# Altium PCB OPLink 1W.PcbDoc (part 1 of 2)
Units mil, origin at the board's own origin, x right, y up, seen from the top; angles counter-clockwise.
Board outline 1023.62 x 1417.32 mil, 4 copper layers (Top Layer, PWR Layer, GND Layer, Bottom Layer), stack 89.2 mil thick; 64 components, 74 nets, 299 pads, 144 vias.
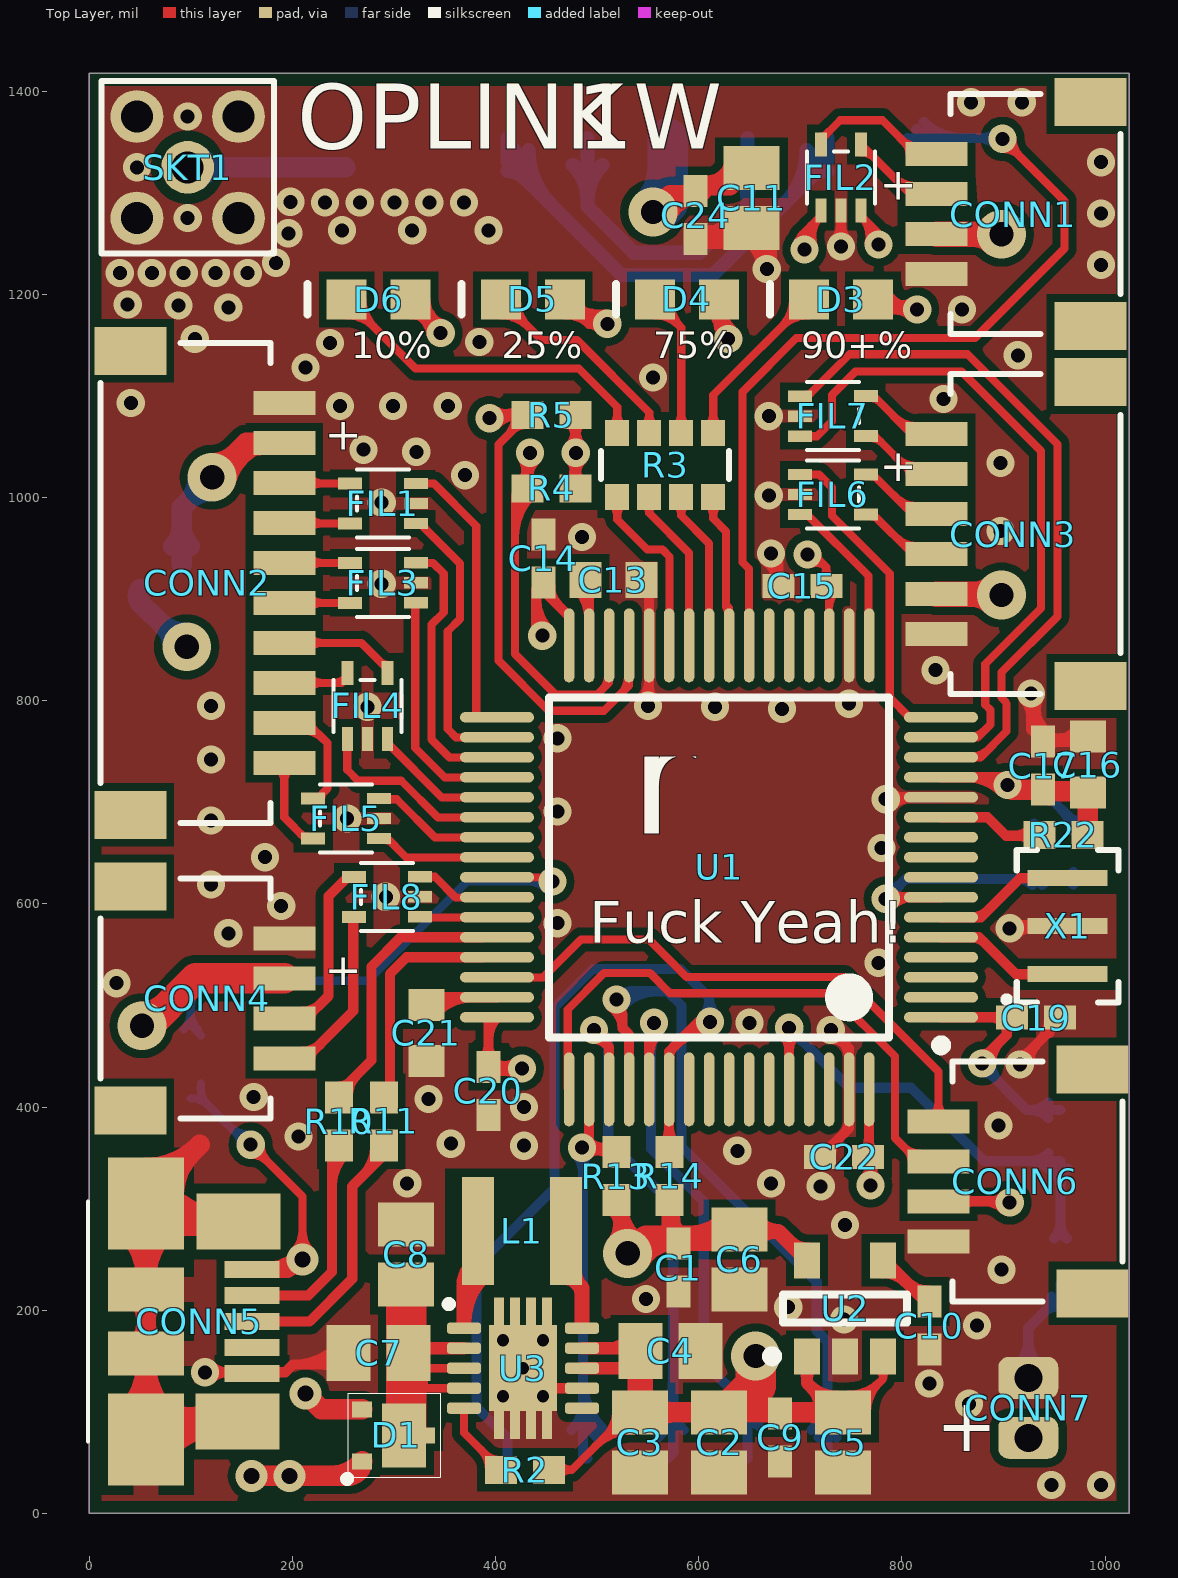
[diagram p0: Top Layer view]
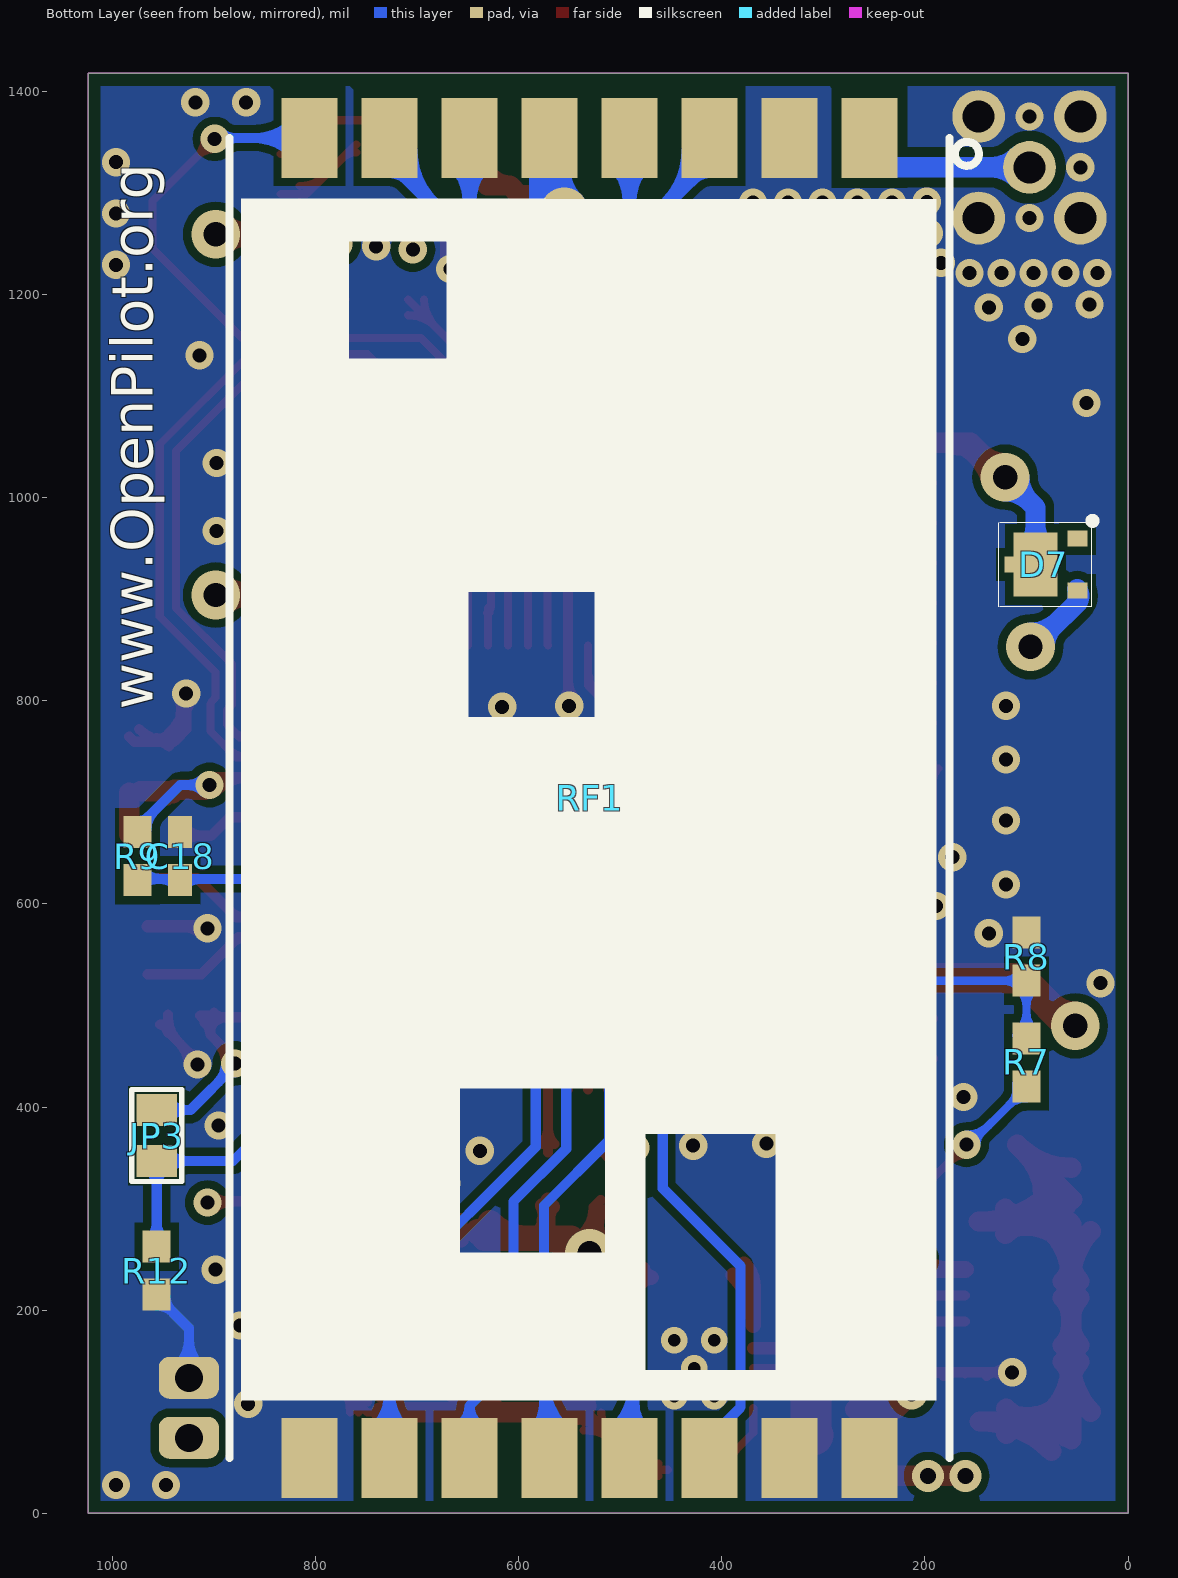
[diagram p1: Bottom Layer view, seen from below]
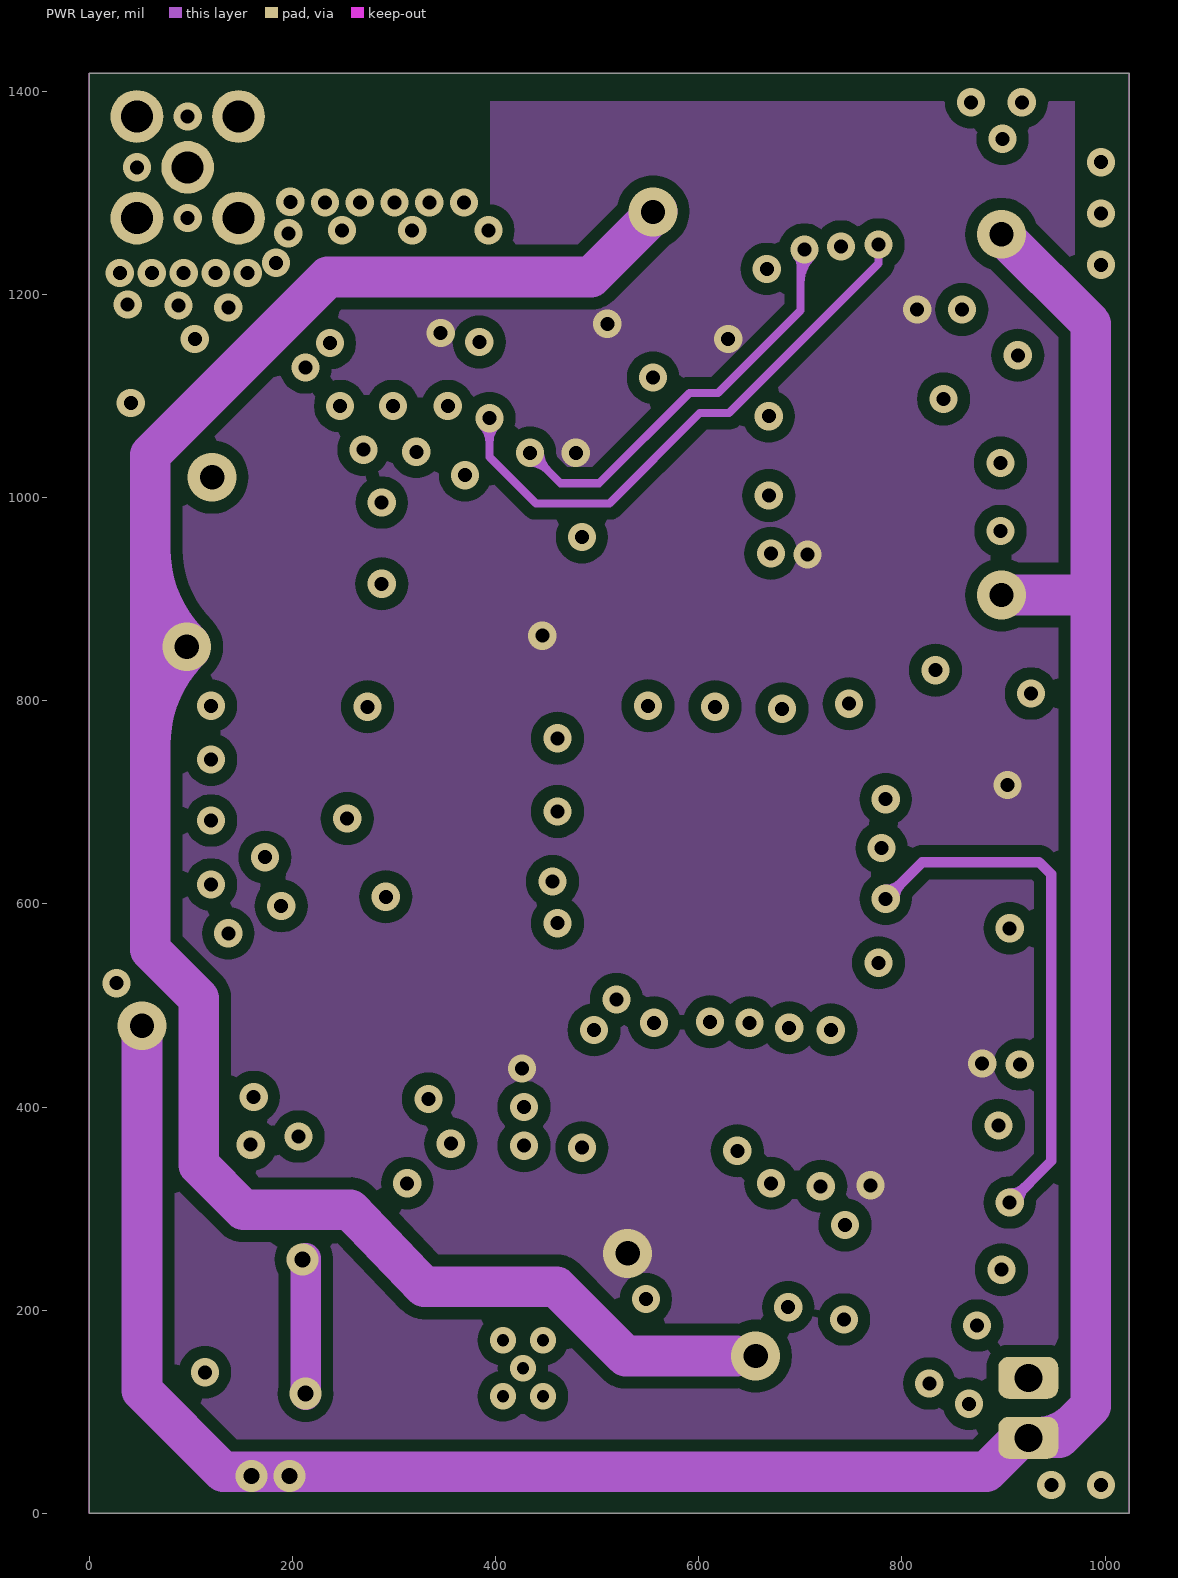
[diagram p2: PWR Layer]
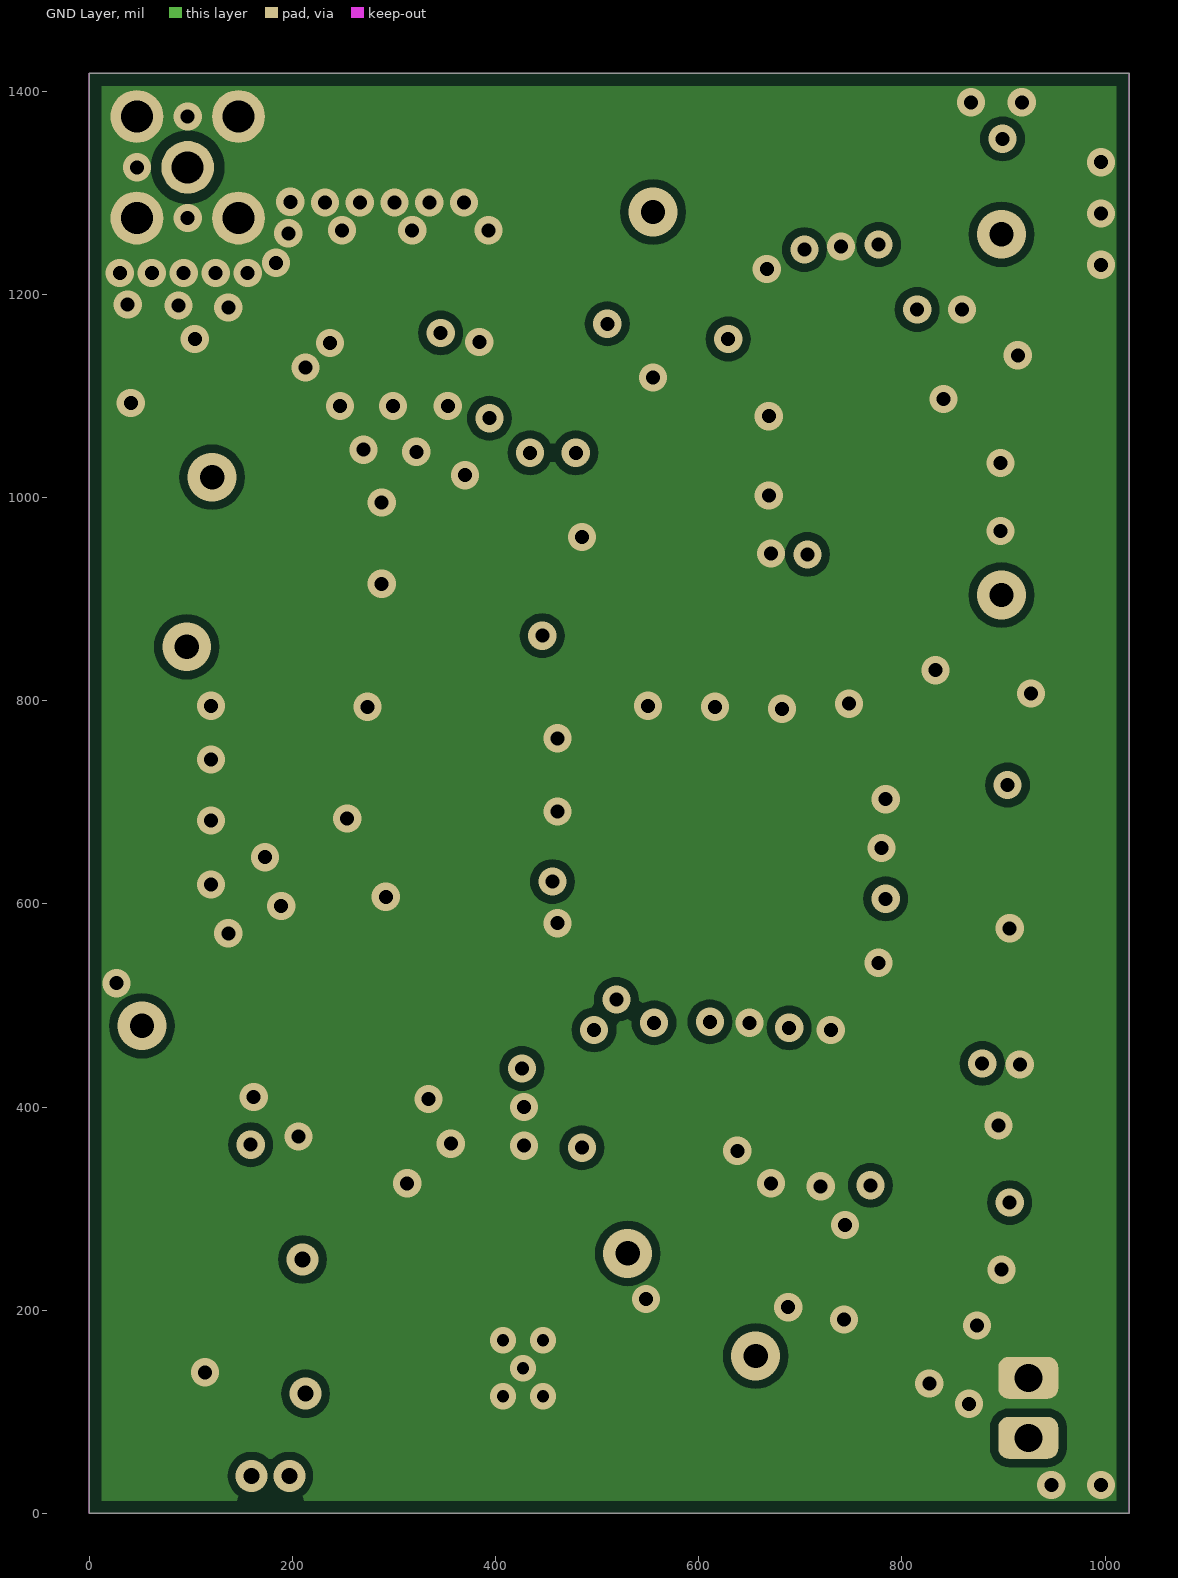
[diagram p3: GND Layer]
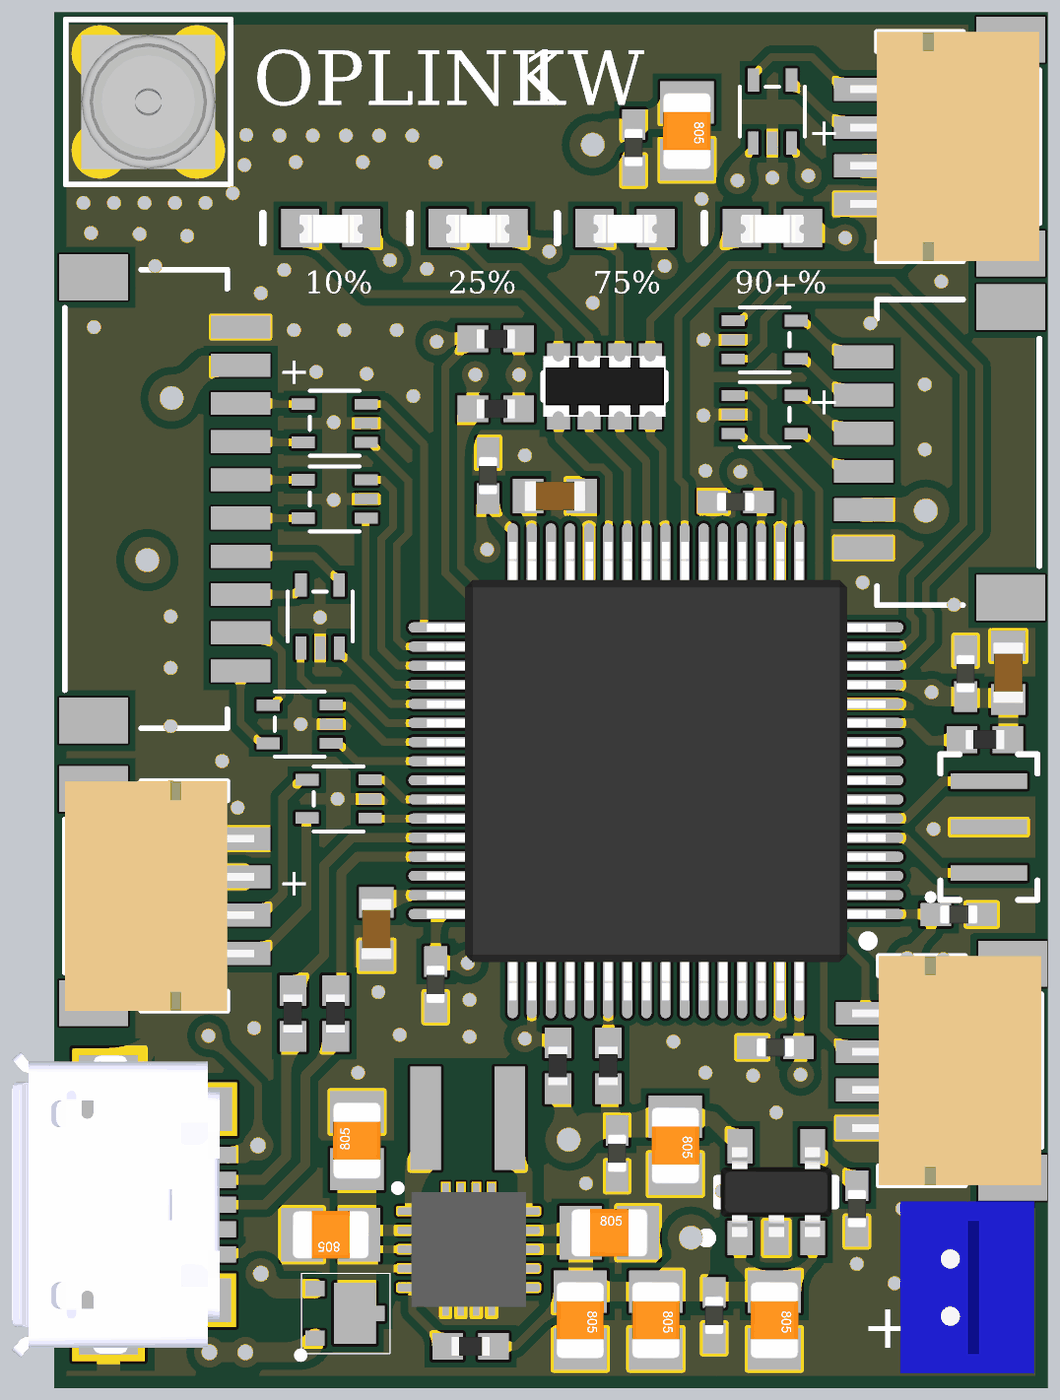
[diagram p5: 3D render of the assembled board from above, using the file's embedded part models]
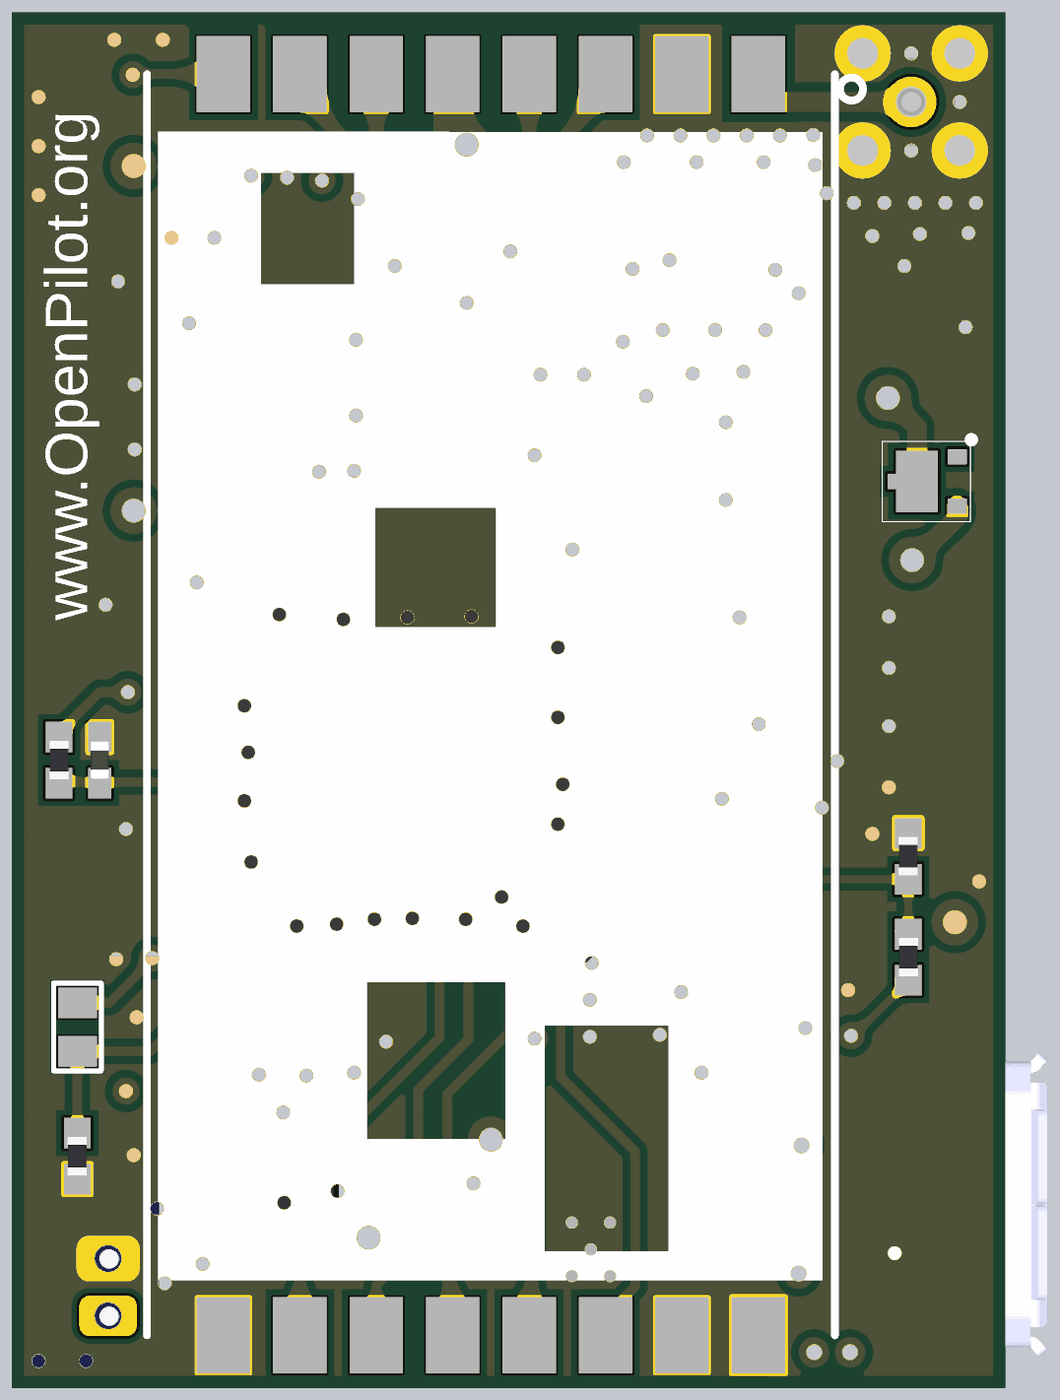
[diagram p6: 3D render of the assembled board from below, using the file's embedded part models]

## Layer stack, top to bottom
Top Layer: signal copper 1.4
Dielectric: core 58.4, FR-4, Dk 4.8
PWR Layer: signal copper 1.4
Dielectric: prepreg 12.6, FR-4, Dk 4.8
GND Layer: signal copper 1.4
Dielectric: core 12.6, FR-4, Dk 4.8
Bottom Layer: signal copper 1.4

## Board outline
0,0 1023.62,0 1023.62,1417.32 0,1417.32

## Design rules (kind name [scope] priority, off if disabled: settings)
AcuteAngle [All] p1: minimum=6.00000000000000E+0001 checktracksonly=FALSE
Clearance CPWG [InNet('ANT') vs InPolygon] p1: gap=10
Clearance Clearance_outline_power [OnLayer('PWR Layer') vs OnLayer('Keep-Out Layer')] p2: gap=15
Clearance Clearance_outline [All vs OnLayer('Keep-Out Layer')] p3: gap=12
Clearance "PWR Layer clearance" [All vs (OnLayer('PWR Layer'))] p4: gap=12
Clearance "Small Parts Clearance Poly" [(HasFootprint('SON-10') OR HasFootprint('TC164')) vs InPolygon] p5: gap=8
Clearance "Small Parts Clearance" [(HasFootprint('SON-10') OR HasFootprint('TC164'))] p6: gap=5
Clearance [All] p7: gap=8
ComponentClearance ComponentClearance_servo_headers [InComponent('JP1') or InComponent('JP2') or InComponent('JP3') or InComponent('JP4') or InComponent('JP5') or InComponent('JP6')] p1: gap=5 collisioncheckmode=3 verticalgap=10 showdistances=FALSE
ComponentClearance [All] p2: gap=10 collisioncheckmode=3 verticalgap=10 showdistances=FALSE
DiffPairsRouting [All] p1: maxlimit=20 minlimit=6 mostfreqgap=10 midlayer1_mingap=10 midlayer1_maxgap=10 midlayer2_mingap=10 midlayer2_maxgap=10 maxuncoupledlength=500
HoleSize [All] p1: absolutevalues=TRUE maxlimit=1000 minlimit=12 maxpercent=80.000 minpercent=20.000
MinimumSolderMaskSliver MinimumSolderMaskSliver_FIL1-3 [InComponent('FIL1') or InComponent('FIL2') or InComponent('FIL3')] p1: minsoldermaskwidth=1
MinimumSolderMaskSliver [All] p2: minsoldermaskwidth=3
PlaneClearance [All] p1: clearance=15
PlaneConnect [All] p1: planeconnectstyle=Direct reliefexpansion=20 reliefentries=4 reliefconductorwidth=10 reliefairgap=10
PolygonConnect PolygonConnect_usb [InComponent('CONN5')] p1: connectstyle=Relief reliefconductorwidth=24 reliefentries=4 polygonreliefangle="90 Angle" airgapwidth=10
PolygonConnect [All] p2: connectstyle=Direct reliefconductorwidth=12 reliefentries=4 polygonreliefangle="90 Angle" airgapwidth=10
RoutingVias [All] p1: holewidth=12 width=28 viastyle="Through Hole" minholewidth=12 minwidth=28 maxholewidth=28 maxwidth=50
SilkToSilkClearance SilkToSilkClearance_text [IsText] p1: silktosilkclearance=0
SilkToSilkClearance [All] p2: silktosilkclearance=4
SilkscreenOverComponentPads [All] p1: minsilkscreentomaskgap=2
SolderMaskExpansion [All] p1: expansion=3
Width [All] p1: maxlimit=400 minlimit=8 preferedwidth=10
20 further rules are at their usual default settings.

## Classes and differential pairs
differential pair USB_R: +USB_R_P -USB_R_N

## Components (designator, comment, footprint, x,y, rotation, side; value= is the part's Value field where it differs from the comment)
C1 "10n" CAP402N 580,242 r270 top
C2 "Cap805" CAP805L 620,70 r270 top
C3 "Cap805" CAP805L 542,70 r270 top
C4 "Cap805" CAP805L 572,160 r0 top
C5 "Cap805" CAP805L 742,70 r270 top
C6 "Cap805" CAP805L 640,250 r270 top
C7 "Cap805" CAP805L 285,158 r180 top
C8 "Cap805" CAP805L 312,255 r90 top
C9 "10n" CAP402N 680,75 r270 top
C10 "10n" CAP402N 827,185 r270 top
C11 "Cap805" CAP805L 652,1295 r270 top
C13 "Cap603" CAP603L 516,919 r180 top
C14 "Cap402" CAP402N 447,940 r90 top
C15 "Cap402" CAP402N 702,913 r0 top
C16 "Cap603" CAP603L 983,737 r270 top
C17 "10n" CAP402N 939,736 r90 top
C18 "Cap402" CAP402N 933,647 r270 bottom
C19 "Cap402" CAP402N 932,488 r180 top
C20 "Cap402" CAP402N 393,416 r270 top
C21 "Cap603" CAP603L 332,473 r90 top
C22 "Cap402" CAP402N 743,351 r180 top
C24 "Cap402" CAP402N 597,1278 r90 top
CONN1 "Flexi Port" "JST SH 4 Pin Side Entry" 1015,1279 r90 top
CONN2 "Flexi-IO" "JST SH 10 PIN SIDE ENTRY" 11,916 r270 top
CONN3 "UART 2 / 4 x ADC" "JST SH 6 Pin Side Entry" 1015,964 r90 top
CONN4 "Main USART" "JST SH 4 Pin Side Entry" 11,507 r270 top
CONN5 "Micro USB B" Micro_USB 56,189 r270 top
CONN6 "SWD" "JST SH 4 Pin Side Entry" 1017,327 r90 top
CONN7 "Power" "JST ZH 2 PIN TOP ENTRY" 1011,104 r90 top
D1 "PMEG2020CPA,115" 3-HUSON 310,77 r90 top
D3 "Green" LED603N 740,1195 r0 top
D4 "Yellow" LED603N 588.33,1195 r0 top
D5 "Orange" LED603N 436.67,1195 r0 top
D6 "Red" LED603N 285,1195 r0 top
D7 "PMEG2020CPA,115" 3-HUSON 91,934 r270 bottom
FIL1 "IP4256CZ5-W,115" SOT-665 289,994 r180 top
FIL2 "IP4256CZ5-W,115" SOT-665 740,1315 r90 top
FIL3 "IP4256CZ5-W,115" SOT-665 289,916 r180 top
FIL4 "IP4256CZ5-W,115" SOT-665 274,795 r90 top
FIL5 "IP4256CZ5-W,115" SOT-665 253,684 r180 top
FIL6 "IP4256CZ5-W,115" SOT-665 732,1003 r0 top
FIL7 "IP4256CZ5-W,115" SOT-665 732,1080 r0 top
FIL8 "IP4256CZ5-W,115" SOT-665 293,607 r180 top
JP3 "SBL" "TOUCH JMP 2PAD" 956,372 r0 bottom
L1 "1.5µH" IND-ASPI-3012S 426,278 r0 top
R2 "Res402" RES402N 429,43 r180 top
R3 "Res Array 330R 1206" TC164 567,1032 r0 top
R4 "Res402" RES402N 455,1009 r0 top
R5 "Res402" RES402N 455,1081 r0 top
R7 "Res402" RES402N 100,444 r90 bottom
R8 "Res402" RES402N 100,548 r270 bottom
R9 "Res402" RES402N 975,647 r90 bottom
R10 "Res402" RES402N 246,386 r270 top
R11 "Res402" RES402N 290,386 r270 top
R12 "Res402" RES402N 956,239 r270 bottom
R13 "Res402" RES402N 519,332 r270 top
R14 "Res402" RES402N 571,332 r270 top
R22 "Res402" RES402N 959,668 r180 top
RF1 "RFM23BP-S2" RFM23BP-S2 530,704 r270 bottom
SKT1 "MMCX Thru hole" MMCX_SOCKET 97,1325 r0 top
U1 "STM32F405RGT6" "STM32 64 Lead" 620,636 r180 top
U2 "LP2992-3.3" SOT23-5L 744,202 r90 top
U3 "TPS63061" SON-10 427,143 r270 top
X1 "8Mhz Ceralock" "CERALOCK 8Mhz" 963,578 r90 top

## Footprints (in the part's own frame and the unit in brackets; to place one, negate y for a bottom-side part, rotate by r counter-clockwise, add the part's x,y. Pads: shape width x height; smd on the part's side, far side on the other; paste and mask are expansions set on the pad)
3-HUSON [mm] "NXP Diode - PMEG2020CPA,115"
  rect 0.4x0.5 smd: 1(-0.65,1.05) 2(0.65,1.05)
  rect 1.6x1.1 smd: 3(0,0)
  rect 0.4x0.25 smd: 3(0,-0.65)
  silkscreen extent -1.14,-0.91 1.05,1.47, body extent -1.04,-0.91 1.04,1.4, height 0.58
CAP402N [mm] "Chip Capacitor, Body 1.0x0.5mm, IPC Medium Density"
  rect 0.8x0.6 smd: 1(-0.6,0) 2(0.6,0)
  body extent -0.5,-0.25 0.5,0.25, height 0.6
CAP603L [mm] "Chip Capacitor, Body 1.6x0.8mm, IPC High Density"
  rect 0.8x0.9 smd: 1(-0.7,0) 2(0.7,0)
  body extent -0.8,-0.4 0.8,0.4, height 0.77
CAP805L [mm] "Chip Capacitor, Body 2.0x1.3mm, IPC High Density"
  rect 1.1x1.4 smd: 1(-0.75,0) 2(0.75,0)
  body extent -1,-0.62 1,0.63, height 0.78
"CERALOCK 8Mhz" [mm] "Digikey 490-1195-1-ND"
  rect 0.4x2 smd: 1(-1.2,0) 2(1.2,0) 3(0,0)
  silkscreen extent -1.91,-1.27 1.91,1.58, body extent -1.78,-1.14 1.78,1.14, height 0.5
IND-ASPI-3012S [mm] "Inductor, Power Body 3.0x3.0x1.2mm DK: ASPI-3012S-1R5N-TCT-ND"
  rect 0.8x2.7 smd: 1(-1.1,0) 2(1.1,0)
  body extent -1.5,-1.65 1.5,1.65, height 1.4
"JST SH 4 Pin Side Entry" [mm] "SM04B-SRSS-TB"
  rect 1.2x1.8 smd paste+0 mask+0.051: 0(-2.8,0.75) 0(2.8,0.75)
  rect 0.6x1.55 smd paste+0 mask+0.051: 1(-1.5,4.6) 2(-0.5,4.6) 3(0.5,4.6) 4(1.5,4.6)
  silkscreen extent -3,0 3,4.25, body extent -3,0 3,4.95, height 2.92
"JST SH 6 Pin Side Entry" [mm] "SM06B-SRSS-TB"
  rect 1.2x1.8 smd paste+0 mask+0.051: 0(-3.8,0.75) 0(3.8,0.75)
  rect 0.6x1.55 smd paste+0 mask+0.051: 1(-2.5,4.6) 2(-1.5,4.6) 3(-0.5,4.6) 4(0.5,4.6) 5(1.5,4.6) 6(2.5,4.6)
  silkscreen extent -4,0 4,4.25, body extent -4,0 4,4.3, height 2.9
"JST SH 10 PIN SIDE ENTRY" [mm] "SM10B-SRSS-TB"
  rect 1.2x1.8 smd paste+0 mask+0.051: 0(-5.8,0.75) 0(5.8,0.75)
  rect 0.6x1.55 smd paste+0 mask+0.051: 1(-4.5,4.6) 2(-3.5,4.6) 3(-2.5,4.6) 4(-1.5,4.6) 5(-0.5,4.6) 6(0.5,4.6) 7(1.5,4.6) 8(2.5,4.6) 9(3.5,4.6) 10(4.5,4.6)
  silkscreen extent -6,0 6,4.25, body extent -6,0 6,4.25, height 2.9
"JST ZH 2 PIN TOP ENTRY" [mm] "B2B-ZR(LF)(SN) 455-1657-ND"
  rrect50% 1.05x1.5 hole 0.7 paste+0 mask+0.076: 1(-0.75,2.2) 2(0.75,2.2)
  body extent -2.26,0.03 2.24,3.53, height 4.5
LED603N [mm] "Chip LED, Body 1.6x0.8mm, IPC Medium Density"
  rect 1x1 smd: 1(-0.8,0) 2(0.8,0)
  silkscreen extent -1.78,-0.38 -1.78,0.38, body extent -0.82,-0.38 0.82,0.34, height 0.68
Micro_USB [mm] "Digikey WM17141CT-ND"
  rect 2.3x1.9 smd paste-0.178: 0(-2.946,0) 0(2.946,0)
  rect 1.4x2.1 smd paste-0.127: 0(-2.5,2.311) 0(2.5,2.286)
  rect 1.1x1.9 smd paste-0.254: 0(-0.8,0) 0(0.8,0)
  rect 0.425x1.38 smd mask+0.064: 1(-1.3,2.65) 2(-0.65,2.65) 3(0,2.65) 4(0.65,2.65) 5(1.3,2.65)
  silkscreen extent -3,-1.45 3,-1.45, body extent -3.99,-2.53 3.99,2.9, height 2.69
MMCX_SOCKET [mil] "Digikey ARF1729-ND and 07248"
  round 52 hole 31.5: 1(0,0) 2(-50,-50) 2(-50,50) 2(50,-50) 2(50,50)
  silkscreen extent -85,-85 85,85, body extent -69,-69 69,69, height 177
RES402N [mm] "Chip Resistor, Body 1.1x0.5mm, IPC Medium Density"
  rect 0.8x0.7 smd: 1(-0.6,0) 2(0.6,0)
  body extent -0.5,-0.25 0.5,0.25, height 0.27
RFM23BP-S2 [mm] "RFM23BP-S2"
  rect 2x1.4 smd mask+0.051: 1(-16.5,7) 2(-16.5,5) 3(-16.5,3) 4(-16.5,1) 5(-16.5,-1) 6(-16.5,-3) 7(-16.5,-5) 8(-16.5,-7) 9(16.5,-7) 10(16.5,-5) 11(16.5,-3) 12(16.5,-1) 13(16.5,1) 14(16.5,3) 15(16.5,5)
  rect 2x1.4 smd: 16(16.5,7)
  silkscreen extent -16.5,-9 16.5,9.73, body extent -16.5,-9 16.5,9, height 1.9
SON-10 [mm] "SON, 10-Leads, Body 3x3 mm, Pitch 0.5mm, IPC High Density"
  rect 0.7x0.25 smd paste-0.04 mask+0.051: 0(-1.422,0.6) 0(-1.422,-0.2) 0(-1.422,0.2) 0(-1.422,-0.6) 0(1.422,0.6) 0(1.422,-0.2) 0(1.422,0.2) 0(1.422,-0.6)
  rect 2.15x1.7 smd paste-0.076 mask+0.051: 0(0,0)
  rrect50% 0.28x0.85 smd paste-0.04 mask+0.064: 1(-1,-1.475) 2(-0.5,-1.475) 3(0,-1.475) 4(0.5,-1.475) 5(1,-1.475) 9(-0.5,1.475) 10(-1,1.475)
  rrect50% 0.28x0.85 smd paste-0.04 mask+0.07: 6(1,1.475) 7(0.5,1.475) 8(0,1.475)
  silkscreen extent -1.65,-1.91 -1.55,-1.8, body extent -1.5,-1.5 1.5,1.5, height 0.75
SOT23-5L [mm] "SOT23, 5-Leads, Body 2.9x1.6mm, Pitch 0.95mm, Lead Span 2.8mm, IPC High Density"
  rect 0.9x0.65 smd mask+0.076: 1(-1.2,0.95) 2(-1.2,0) 3(-1.2,-0.95) 4(1.2,-0.95) 5(1.2,0.95)
  silkscreen extent -1.32,-1.55 0.35,1.95, body extent -1.17,-1.46 1.17,1.46, height 0.97
SOT-665 [mm] "NXP SOT665"
  rect 0.6x0.28 smd mask+0.076: 1(-0.825,0.5) 2(-0.825,0) 3(-0.825,-0.5)
  rect 0.6x0.3 smd mask+0.076: 4(0.825,-0.5) 5(0.825,0.5)
  silkscreen extent -0.65,-0.85 0.65,0.85, body extent -0.65,-0.85 0.65,0.85, height 0.6
"STM32 64 Lead" [mm] "Thin QFP, 64-Leads, Body 10x10mm, Pitch 0.5mm, IPC Medium Density"
  oval 1.85x0.265 smd mask+0.076: 1(-5.55,3.75) 2(-5.55,3.25) 3(-5.55,2.75) 4(-5.55,2.25) 5(-5.55,1.75) 6(-5.55,1.25) 7(-5.55,0.75) 8(-5.55,0.25) 9(-5.55,-0.25) 10(-5.55,-0.75) 11(-5.55,-1.25) 12(-5.55,-1.75) 13(-5.55,-2.25) 14(-5.55,-2.75) 15(-5.55,-3.25) 16(-5.55,-3.75) 33(5.55,-3.75) 34(5.55,-3.25) 35(5.55,-2.75) 36(5.55,-2.25) 37(5.55,-1.75) 38(5.55,-1.25) 39(5.55,-0.75) 40(5.55,-0.25) 41(5.55,0.25) 42(5.55,0.75) 43(5.55,1.25) 44(5.55,1.75) 45(5.55,2.25) 46(5.55,2.75) 47(5.55,3.25) 48(5.55,3.75)
  oval 0.265x1.85 smd mask+0.076: 17(-3.75,-5.55) 18(-3.25,-5.55) 19(-2.75,-5.55) 20(-2.25,-5.55) 21(-1.75,-5.55) 22(-1.25,-5.55) 23(-0.75,-5.55) 24(-0.25,-5.55) 25(0.25,-5.55) 26(0.75,-5.55) 27(1.25,-5.55) 28(1.75,-5.55) 29(2.25,-5.55) 30(2.75,-5.55) 31(3.25,-5.55) 32(3.75,-5.55) 49(3.75,5.55) 50(3.25,5.55) 51(2.75,5.55) 52(2.25,5.55) 53(1.75,5.55) 54(1.25,5.55) 55(0.75,5.55) 56(0.25,5.55) 57(-0.25,5.55) 58(-0.75,5.55) 59(-1.25,5.55) 60(-1.75,5.55) 61(-2.25,5.55) 62(-2.75,5.55) 63(-3.25,5.55) 64(-3.75,5.55)
  silkscreen extent -5.68,-4.25 4.25,4.57, body extent -6.01,-5.99 5.99,6.01, height 1.7
TC164 [mm] "4-Resistor Array"
  rect 0.6x0.65 smd mask+0.064: 1(-1.2,-0.8) 2(-0.4,-0.8) 3(0.4,-0.8) 4(1.2,-0.8) 5(1.2,0.8) 6(0.4,0.8) 7(-0.4,0.8) 8(-1.2,0.8)
  silkscreen extent -1.6,-0.35 1.6,0.35, body extent -1.6,-0.8 1.6,0.8, height 0.55
"TOUCH JMP 2PAD" [mil] "Touch Jumper 2 Pad"
  rect 40x31.5 smd mask+2: 1(0,25) 2(0,-25)
  silkscreen extent -25,-45 25,45

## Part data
C1 C9 C10 C17: library part Cap402, "Capacitor SMD"
C2 C3 C4 C5 C6 C7 C8 C11 C13 C14 C15 C16 C18 C19 C20 C21 C22 C24: "Capacitor SMD"
CONN1 CONN4 CONN6: library part "JST-SH 4-pin Side Entry Socket", "JST-SH 4-pin Side Entry Socket"
CONN2: library part "JST-SH 10-pin Side Entry Socket", "JST-SH 10-pin Side Entry Socket"
CONN3: library part "JST-SH 6-pin Side Entry Socket", "JST-SH 6-pin Side Entry Socket"
CONN5: library part "USB Micro B SMT", "USB Micro B SMT Socket"
CONN7: library part "JST ZH 2-pin Top Entry Socket", "JST ZH 1.5mm 2-pin TopEntry Socket"
D1 D7: "Dual Diode Command Cathode 2A"
D3: library part "LED 603 Gr", "Green 603 LED"
D4: library part "LED 603 Yellow", "Yellow 603 LED"
D5: library part "LED 603 Or", "Orange 603 LED"
D6: library part "LED 603 Red", "Red 603 LED"
FIL1 FIL2 FIL3 FIL4 FIL5 FIL6 FIL7 FIL8: library part "RF Filter 100R 30pF", "IP4256CZ5-W,115 2 channel, 100R, 30pF, RF ESD Filter"
JP3: library part "2 PAD Touch JMP", "2 Pad Touch Jumper"
L1: library part "Pwr Inductor 1.5µH", "Power Inductor 1.5µH"
R2 R4 R5 R7 R8 R9 R10 R11 R12 R13 R14 R22: "Resistor SMD"
R3: library part "Res Array 330R", "4 Resistor Array"
RF1: "UHF 1W Transceiver"
SKT1: "MMCX Socket"
U1: library part STM32F103RET6, "STM32 ARM-based 32-bit MCU with 1MB Flash, 64-pin LQFP, Industrial Temperature"
U2: "3.3V 250mA LDO Regulator"
X1: library part CERALOCK8, "Ceralock 8Mhz with caps"

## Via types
v1: diameter 27.8, hole 13.78, Top Layer to Bottom Layer, tented both sides, 127 vias
v2: diameter 48, hole 24, Top Layer to Bottom Layer, tented both sides, 8 vias
v3: diameter 31.5, hole 15.75, Top Layer to Bottom Layer, tented both sides, 4 vias
v4: diameter 25.98, hole 12, Top Layer to Bottom Layer, tented bottom, 4 vias
v5: diameter 26, hole 12, Top Layer to Bottom Layer, tented bottom, 1 vias

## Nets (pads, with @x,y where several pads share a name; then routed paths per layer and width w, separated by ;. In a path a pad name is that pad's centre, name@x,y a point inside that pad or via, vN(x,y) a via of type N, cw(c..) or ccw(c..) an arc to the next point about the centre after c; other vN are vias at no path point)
ANT: RF1.1 SKT1.1 | length 215.7
  Bottom Layer w20: SKT1.1@97,1325 RF1.1@252,1325 ; SKT1.1@108.31,1313.69 cw(c135.63,1286.37) 135.63,1325 cw(c135.63,1363.63) SKT1.1@108.31,1336.31
GND: C1.2 C2.2 C3.2 C4.2 C5.2 C6.2 C7.2 C8.2 C9.2 C10.2 C11.2 C13.1 C14.2 C15.1 C16.1 C17.2 C18.1 C19.1 C20.2 C21.1 C22.2 C24.1 CONN1.1 CONN2.1 CONN3.1 CONN4.1 CONN5.0 CONN5.5 CONN6.1 CONN7.2 FIL1.2 FIL2.2 FIL3.2 FIL4.2 FIL5.2 FIL6.2 FIL7.2 FIL8.2 R8.1 R12.2 RF1.2 RF1.9 RF1.15 RF1.16 SKT1.2 U1.12 U1.18 U1.28 U1.63 U2.2 U3.0 U3.7 X1.3 | length 3538
  Top Layer w10: v1(114,139) 159.15,139 CONN5.5@160.33,137.82 161.51,139 193,139 200.75,146.75 244.22,146.75 C7.2@255.47,158 ; v1@120.29,132.71 cw(c135.48,117.52) 135.48,139 cw(c135.48,160.48) v1@120.29,145.29 ; 130.55,139 cw(c130.55,126.84) CONN5.5@139.15,135.44 ; CONN5.5@181.51,135.44 cw(c190.11,126.84) 190.11,139 ; 202.36,146.75 ccw(c202.36,205.21) C7.2@243.7,163.87 ; 226.5,146.75 ccw(c226.5,181.06) C7.2@250.77,156.8 ; 228.17,146.75 cw(c228.17,124.8) C7.2@243.7,140.32 ; v5(427,143) 446.68,123.32 U3.7@485.07,123.32 ; C13.1@543.56,919 551.1,911.46 U1.28@551.1,854.5 551.1,796.1 v1(550,795) ; v1@543.71,801.29 ccw(c525.86,819.14) U1.28@551.1,819.14 ; 551.1,813.82 ccw(c568.82,813.82) v1@556.29,801.29 ; v1@665.61,937.92 cw(c646.01,912.16) C15.1@678.38,912.16 ; v1(671,945) 678.38,937.62 C15.1@678.38,913 ; v1@671.67,945.88 cw(c661.36,932.34) 678.38,932.34 ; C15.1@673.56,917.82 ccw(c661.93,929.44) 678.38,929.44 ccw(c694.82,929.44) C15.1@683.19,917.82 ; C22.2@722.38,355 724,355 747.95,378.95 U1.63@747.95,417.5 747.95,458.05 v1(730,476) ; v1@730,467.1 cw(c730,445.62) 745.19,460.81 cw(c760.38,476) v1@738.9,476 ; C22.2@730.13,351 cw(c754.57,351) 737.29,368.29 ; v1@732.07,467.35 cw(c734.2,458.44) 742.13,463.02 ; v1@733.71,1253.29 ccw(c718.52,1268.48) 740,1268.48 ccw(c761.48,1268.48) v1@746.29,1253.29 ; v1(740,1247) FIL2.2@740,1282.52 ; 740.97,465.03 cw(c724.64,448.7) U1.63@747.74,448.7 ; 742.39,373.39 ccw(c729.49,386.3) U1.63@747.74,386.3 ; v1(784,703) 785.9,704.9 U1.12@838.5,704.9 ; v1@790.29,696.71 cw(c810.06,676.94) U1.12@810.06,704.9 ; v1@790.29,709.29 ccw(c800.9,719.9) 800.9,704.9 ; v1(906,576) v1@908,578 ; v1@916,450.9 ccw(c916,464.22) 925.42,454.8 ; v1@916.31,445.69 945,474.38 ; v1@920.71,800.71 cw(c905.52,785.52) 927,785.52 cw(c948.48,785.52) v1@933.29,800.71 ; v1@922.55,799.29 cw(c911.81,780.69) 932.56,786.25 cw(c953.31,791.81) v1@934.71,802.55 ; v1@924.9,442 cw(c954.53,442) 933.58,462.96 ; 927,783.91 ccw(c958.09,783.91) C17.2@936.82,761.23 ; 935.15,464.53 ccw(c911.68,488) C19.1@944.87,488 ; C17.2@936.32,769.82 cw(c932.99,777.61) 927,771.62 ; C17.2@943.16,759.62 ccw(c943.16,802.43) C16.1@973.43,772.16 ; C17.2@943.66,768.53 cw(c979.75,807) v1(927,807) 927,771.62 ; C17.2@943.82,754.81 cw(c955.44,743.18) 955.44,759.62 cw(c955.44,776.07) C17.2@943.82,764.44 ; C17.2@944.58,767.47 ccw(c953.56,773.77) 956.4,763.17 ; 945,472.83 cw(c953.47,472.83) C19.1@952.48,481.24 ; C19.1@945,491 945,474.38 ; C19.1@946,484.25 cw(c939.45,479.93) 945,474.38 ; C16.1@983,764.56 978.06,759.62 C17.2@939,759.62 927,771.62
  Top Layer w12: v1@908,578 X1.3@965,578 ; v1@911.58,570.42 cw(c929.89,552.11) X1.3@929.89,578 ; v1@911.58,581.58 ccw(c920.24,590.24) 920.24,578
  Top Layer w20: CONN5.0@36.62,100.25 ccw(c-10.15,147.03) 56,147.03 ccw(c122.15,147.03) 75.38,100.25 ccw(c98.73,123.61) 98.73,90.57 ; CONN5.0@36.62,277.75 cw(c-10.15,230.97) 56,230.97 cw(c122.15,230.97) 75.38,277.75 cw(c98.73,254.39) 98.73,287.43 ; CONN5.0@47.76,149.26 cw(c27.87,129.37) 56,129.37 cw(c84.13,129.37) CONN5.0@64.24,149.26 ; CONN5.0@47.76,165.74 ccw(c27.87,185.64) 56,185.64 ccw(c84.13,185.64) CONN5.0@64.24,165.74 ; CONN5.0@47.76,212.26 cw(c27.87,192.36) 56,192.36 cw(c84.13,192.36) CONN5.0@64.24,212.26 ; CONN5.0@47.76,228.74 ccw(c27.87,248.63) 56,248.63 ccw(c84.13,248.63) CONN5.0@64.24,228.74 ; CONN5.0@55,309 109,363 ; CONN5.0@56,340.28 ccw(c56,413.37) 107.68,361.68 ; CONN5.0@61.23,75.64 cw(c97.29,39.59) 97.29,90.57 ; CONN5.0@61.23,302.36 ccw(c97.29,338.41) 97.29,287.43 ; CONN5.0@71.49,103.47 ccw(c99.32,144.05) 112.05,96.53 ccw(c124.23,51.09) CONN5.0@81.11,69.91 ; CONN5.0@71.51,274.53 cw(c99.72,233.44) 112.62,281.59 cw(c125.19,328.5) CONN5.0@80.96,308.44 ; CONN5.0@75.38,61.5 cw(c145.57,-8.7) CONN5.0@145.57,90.57 ; CONN5.0@75.38,316.5 ccw(c145.57,386.7) CONN5.0@145.57,287.43 ; CONN5.0@83.4,312.87 cw(c142.62,312.87) 100.74,354.75 ; CONN5.0@119.8,78.16 ccw(c89.83,48.18) 89.83,90.57 ccw(c89.83,132.97) CONN5.0@119.8,102.99 ; CONN5.0@120.8,275.01 ccw(c90.83,245.03) 90.83,287.43 ccw(c90.83,329.82) CONN5.0@120.8,299.84 ; CONN5.0@146,90.57 73.57,90.57 CONN5.0@56,73 CONN5.0@56,157.5 CONN5.0@56,220.5 56,285 58.43,287.43 CONN5.0@147,287.43 ; C24.1@597.91,1259.88 ccw(c606.58,1274.92) 611.08,1258.15 ; C11.2@637.2,1273.01 cw(c597,1307.07) C24.1@597,1254.38 640.91,1254.38 C11.2@652,1265.47 654.53,1265.47 667,1253 v1(667,1225) ; C11.2@650.92,1256.15 cw(c626.82,1223.99) v1@667,1223.99
  Bottom Layer w10: CONN7.2@913.31,144.61 ccw(c886.56,171.36) 924.39,171.36 ccw(c962.21,171.36) CONN7.2@935.47,144.61 ; CONN7.2@924.39,133.53 924.39,182.39 956,214 R12.2@956,226.38 ; C18.1@930,671.62 C18.1@930,678.96 ; 940,198 cw(c956,182.01) R12.2@956,204.63 ; 941.43,199.43 ccw(c927.45,213.41) R12.2@947.22,213.41
  other v1: 947,28 996,28 866,108 827,128 874,185 743,191 688,203 548,211 898,240 744,284 720,322 313,325 671,325 638,357 428,362 356,364 206,371 895,382 428,400 334,408 162,410 916,442 650,483 27,522 777,542 137,571 461,581 189,598 292,607 120,619 173,646 780,655 120,682 254,684 461,691 120,742 461,763 682,792 274,794 616,794 120,795 748,797 833,830 288,915 485,961 897,967 288,995 669,1002 370,1022 897,1034 322,1045 270,1047 669,1080 247,1090 299,1090 353,1090 41,1093 841,1097 555,1118 213,1128 914,1140 237,1152 384,1153 104,1156 859,1185 137,1187 88,1189 38,1190 30.2,1221 61.65,1221 93.1,1221 124.55,1221 156,1221 996,1229 184,1231 196,1260 249,1263 318,1263 393,1263 97,1275 996,1279.5 232.2,1290.36 266.4,1290.36 300.6,1290.36 334.8,1290.36 369,1290.36 198,1291 47,1325 996,1330 97,1375 868,1389 918,1389
  other v4: 407.32,115.44 446.68,115.44 407.32,170.56 446.68,170.56
GPIO_2: RF1.8 U1.23 | length 1062.5
  Top Layer w8: 643.1,1104.1 643.1,936.27 649.53,929.85 U1.23@649.53,854.5 ; 643.5,1104.5 696,1157 872,1157 960,1245 960,1292 899.5,1352.5 v1@899.5,1353.5 ; v1@899,1343.1 cw(c899,1319.21) 915.9,1336.1 cw(c932.79,1353) v1@908.9,1353
  Bottom Layer w10: RF1.8@805.59,1353.61 RF1.8@813.2,1346 ; RF1.8@811.2,1354 v1@898,1354 ; RF1.8@814.47,1344.73 cw(c836.86,1322.34) 836.86,1354 ; RF1.8@814.47,1362.49 ccw(c834.96,1382.98) 834.96,1354 ; RF1.8@821.54,1337.65 cw(c861,1298.19) 861,1354 ; RF1.8@821.54,1369.56 ccw(c859.1,1407.12) 859.1,1354 ; 875.11,1354 cw(c875.11,1329.11) v1@892.71,1346.71 ; 879.93,1354 ccw(c879.93,1372.07) v1@892.71,1359.29
  other v1: 899,1353
NetC10_1: C10.1 U2.4 | length 114.6
  Top Layer w12: U2.4@781.4,237.53 cw(c781.4,205.97) 803.71,228.29 ; U2.4@781.4,249.24 782.76,249.24 823.38,208.62 C10.1@829,208.62 ; 804.18,227.82 ccw(c827,250.65) C10.1@827,218.37
NetC13_2: C13.2 U1.31 | length 106.7
  Top Layer w10: C13.2@480.84,909.43 cw(c453.79,882.38) U1.31@492.05,882.38 ; C13.2@488.44,919 492.05,915.39 U1.31@492.05,854.5 ; 492.05,899.79 cw(c505.68,899.79) C13.2@496.04,909.43
NetC21_2: C21.2 U1.47 | length 134.6
  Top Layer w10: C21.2@332,500.56 339.49,508.05 U1.47@401.5,508.05 ; C21.2@334.5,500.03 cw(c353.85,480.68) 353.85,508.05 ; C21.2@341.57,492.96 cw(c377.99,456.53) U1.47@377.99,508.05
NetCONN1_3: CONN1.3 FIL2.4 | length 149.2
  Top Layer w8: FIL2.4@759.68,1339.67 cw(c759.68,1320.81) 773.02,1334.15 ; FIL2.4@759.68,1347.48 808.48,1298.68 CONN1.3@833.9,1298.68 ; 790.4,1316.77 ccw(c815.2,1341.57) CONN1.3@815.2,1306.5 ; CONN1.3@804.05,1303.11 ccw(c815.2,1314.25) CONN1.3@815.2,1298.5
NetCONN1_4: CONN1.4 FIL2.5 | length 181.1
  Top Layer w8: FIL2.5@719.52,1342 719.52,1351.52 739.29,1371.29 780.71,1371.29 813.94,1338.06 CONN1.4@833.9,1338.06 ; FIL2.5@720.32,1355.29 ccw(c720.32,1362.48) FIL2.5@725.4,1357.4 ; 799.73,1352.27 ccw(c815.2,1367.75) CONN1.4@815.2,1345.87 ; 802.75,1349.25 cw(c791.55,1338.06) CONN1.4@807.39,1338.06
NetCONN2_2: CONN2.2 D7.3 | length 435.4
  Top Layer w20: v2(121,1020) 154.8,1053.8 CONN2.2@192.1,1053.8 ; v2@121,1034 ccw(c121,1067.8) 144.9,1043.9 ccw(c168.8,1020) v2@135,1020 ; v2@134.52,1016.38 cw(c188.35,1001.95) 160.49,1050.21 ; v2@134.65,1023.11 cw(c149.24,1026.44) 141.76,1039.4 ; 138.55,1037.55 cw(c173.4,1002.69) CONN2.2@173.4,1051.98
  Bottom Layer w20: D7.3@82.76,952.08 ccw(c62.87,971.98) 91,971.98 ccw(c119.13,971.98) D7.3@99.24,952.08 ; D7.3@91,934 91,990 v2(121,1020) ; v2@107,1020 cw(c73.2,1020) 97.1,996.1 cw(c121,972.2) v2@121,1006
NetCONN2_3: CONN2.3 FIL1.4 | length 94.3
  Top Layer w8: CONN2.3@192.1,1014.43 192.84,1013.68 FIL1.4@256.52,1013.68 ; CONN2.3@216.33,1008.9 cw(c227.87,997.35) 227.87,1013.68 ; CONN2.3@216.33,1019.95 ccw(c231.45,1035.07) 231.45,1013.68
NetCONN2_4: CONN2.4 FIL1.5 | length 94.3
  Top Layer w8: CONN2.4@192.1,975.06 192.84,974.32 FIL1.5@256.52,974.32 ; CONN2.4@216.33,969.53 cw(c227.87,957.98) 227.87,974.31 ; CONN2.4@216.33,980.58 ccw(c231.45,995.7) 231.45,974.31
NetCONN2_5: CONN2.5 FIL3.4 | length 94
  Top Layer w8: CONN2.5@192.1,935.68 FIL3.4@256.52,935.68 ; CONN2.5@216.33,930.16 cw(c229.66,916.83) 229.66,935.68 cw(c229.66,954.54) CONN2.5@216.33,941.21
NetCONN2_6: CONN2.6 FIL3.5 | length 94
  Top Layer w8: CONN2.6@192.1,896.32 FIL3.5@256.52,896.32 ; CONN2.6@216.33,890.79 cw(c229.66,877.46) 229.66,896.31 cw(c229.66,915.17) CONN2.6@216.33,901.84
NetCONN2_7: CONN2.7 FIL4.4 | length 153.2
  Top Layer w8: CONN2.7@192.1,856.94 268.06,856.94 293.68,831.32 FIL4.4@293.68,827.48 ; CONN2.7@216.33,851.42 cw(c229.66,838.09) 229.66,856.94 cw(c229.66,875.8) CONN2.7@216.33,862.47 ; 286.9,838.1 ccw(c293.68,844.89) FIL4.4@293.68,835.29
NetCONN2_8: CONN2.8 FIL4.5 | length 112.7
  Top Layer w8: CONN2.8@192.1,817.57 248.57,817.57 254.32,823.32 FIL4.5@254.32,827.48 ; CONN2.8@216.33,812.05 cw(c229.66,798.72) 229.66,817.57 cw(c229.66,836.43) CONN2.8@216.33,823.1 ; 240.06,817.57 ccw(c240.06,835.83) FIL4.5@252.97,822.92
NetCONN2_9: CONN2.9 FIL5.4 | length 148.6
  Top Layer w8: CONN2.9@192.1,778.2 214.6,778.2 234.61,758.19 234.61,713.61 223.5,702.5 FIL5.4@222.5,702.5 ; CONN2.9@210.8,770.39 cw(c210.8,742.37) 230.62,762.19 ; CONN2.9@218.61,778.2 ccw(c228.31,778.2) CONN2.9@221.45,771.35 ; FIL5.4@228.33,703.68 cw(c237.13,703.68) 230.91,709.91
NetCONN2_10: CONN2.10 FIL5.5 | length 127.8
  Top Layer w8: CONN2.10@186.58,733.31 cw(c173.24,719.98) 192.1,719.98 cw(c210.96,719.98) CONN2.10@197.63,733.31 ; CONN2.10@192.1,738.83 192.1,684.9 212.68,664.32 FIL5.5@220.52,664.32 ; 208.07,668.93 ccw(c214.61,675.48) FIL5.5@214.61,666.22
NetCONN3_3: CONN3.3 FIL6.4 | length 115
  Top Layer w8: FIL6.4@764.48,983.32 771.68,983.32 810.68,944.32 CONN3.3@833.9,944.32 ; FIL6.4@770.39,981.41 cw(c770.39,973.67) FIL6.4@775.86,979.14 ; 794.16,960.84 ccw(c815.2,981.88) CONN3.3@815.2,952.13
NetCONN3_4: CONN3.4 FIL6.5 | length 115
  Top Layer w8: FIL6.5@764.48,1022.68 771.32,1022.68 810.32,983.68 CONN3.4@833.9,983.68 ; FIL6.5@770.39,1020.78 cw(c770.39,1013.94) FIL6.5@775.22,1018.78 ; 793.53,1000.47 ccw(c815.2,1022.14) CONN3.4@815.2,991.5
NetCONN3_5: CONN3.5 FIL7.4 | length 124.3
  Top Layer w8: FIL7.4@764.48,1060.32 773.68,1060.32 810.94,1023.06 CONN3.5@833.9,1023.06 ; FIL7.4@770.39,1058.41 cw(c770.39,1045.84) 779.27,1054.73 ; 794.6,1039.4 ccw(c815.2,1059.99) CONN3.5@815.2,1030.87 ; CONN3.5@804.87,1029.13 cw(c798.79,1023.06) CONN3.5@807.39,1023.06
NetCONN3_6: CONN3.6 FIL7.5 | length 117.6
  Top Layer w8: FIL7.5@764.48,1099.68 772.32,1099.68 809.57,1062.43 CONN3.6@833.9,1062.43 ; FIL7.5@770.39,1097.78 cw(c770.39,1088.52) 776.93,1095.07 ; 792.27,1079.73 ccw(c815.2,1102.67) CONN3.6@815.2,1070.24
NetCONN4_3: CONN4.3 FIL8.4 | length 204.1
  Top Layer w10: CONN4.3@192.1,487.32 213.44,487.32 235.71,509.58 235.71,607.71 FIL8.4@255,627 ; CONN4.3@210.8,494.13 ccw(c210.8,516.93) 226.93,500.81 ; CONN4.3@217.61,487.32 cw(c227.69,487.32) CONN4.3@220.57,494.44
NetCONN4_4: CONN4.4 FIL8.5 | length 205.5
  Top Layer w10: CONN4.4@192.1,447.94 213.44,447.94 260,494.51 FIL8.5@260,587 ; CONN4.4@210.8,454.76 ccw(c210.8,477.56) 226.93,461.44 ; CONN4.4@217.61,447.94 cw(c227.69,447.94) CONN4.4@220.57,455.07
NetD3_1: D3.1 R3.5 | length 259.6
  Top Layer w8: R3.5@608.72,1070 ccw(c595.39,1083.34) 614.24,1083.34 ccw(c633.1,1083.34) R3.5@619.77,1070 ; R3.5@614.24,1063.5 614.24,1100.74 D3.1@708.5,1195 ; D3.1@692.82,1195 cw(c654.95,1195) 681.73,1168.22 cw(c708.5,1141.45) D3.1@708.5,1179.32
NetD4_1: D4.1 R3.6 | length 237.6
  Top Layer w8: D4.1@556.84,1179.32 cw(c556.84,1145.88) 580.48,1169.52 ; D4.1@560,1190 582.75,1167.25 ; D4.1@564.51,1194.57 ccw(c583.7,1193.48) D4.1@570.11,1179.89 ; D4.1@572.5,1194.12 ccw(c607.63,1192.13) 582.75,1167.25 ; R3.6@577.22,1070 ccw(c563.89,1083.34) 582.75,1083.34 ccw(c601.61,1083.34) R3.6@588.27,1070 ; R3.6@582.75,1063.5 582.75,1167.25
NetD5_1: D5.1 R3.7 | length 301.5
  Top Layer w8: D5.1@405.17,1179.32 cw(c405.17,1141.45) 431.95,1168.22 cw(c458.72,1195) D5.1@420.86,1195 ; D5.1@405.17,1195 445.31,1154.86 480.14,1154.86 551.25,1083.75 R3.7@551.25,1063.5 ; R3.7@545.73,1070 ccw(c532.39,1083.34) 551.25,1083.34 ccw(c570.11,1083.34) R3.7@556.78,1070
NetD6_1: D6.1 R3.8 | length 424.9
  Top Layer w8: D6.1@253.5,1179.32 cw(c253.5,1141.45) 280.28,1168.22 cw(c307.06,1195) D6.1@269.19,1195 ; D6.1@253.5,1195 321.4,1127.1 481.9,1127.1 519.76,1089.24 R3.8@519.76,1063.5 ; R3.8@514.23,1070 ccw(c500.9,1083.34) 519.76,1083.34 ccw(c538.61,1083.34) R3.8@525.28,1070
NetFIL1_1: FIL1.1 U1.34 | length 286.4
  Top Layer w8: FIL1.1@321.48,974.32 325.68,974.32 365,935 365,880.37 353,868.37 353,772 361.05,763.95 U1.34@401.5,763.95 ; FIL1.1@329.29,974.32 ccw(c338,974.32) 331.84,968.16
NetFIL1_3: FIL1.3 U1.33 | length 264.8
  Top Layer w8: FIL1.3@321.48,1013.68 339.32,1013.68 381,972 U1.33@381,784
